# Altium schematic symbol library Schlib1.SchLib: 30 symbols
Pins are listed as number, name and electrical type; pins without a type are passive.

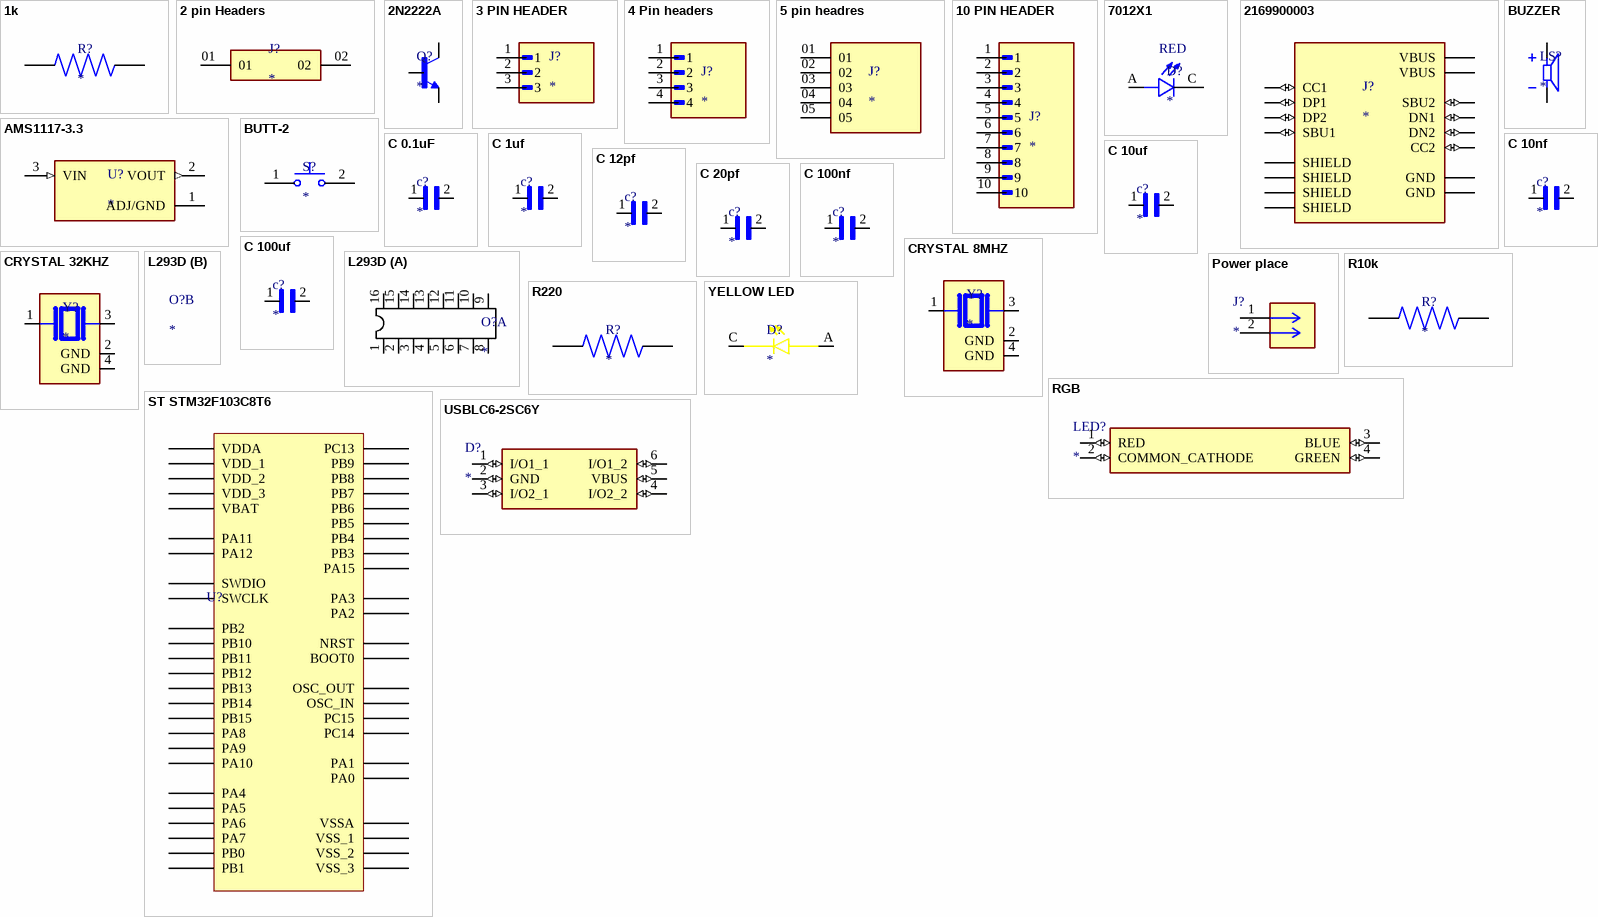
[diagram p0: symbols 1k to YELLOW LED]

## 1k
designator R?
RES, 1K, 1%, 0.1W, 0603, THICK FILM; Resistance: 10kohm; Resistance Tolerance: Â± 1%; Power Rating: 100mW; Resistor Case / Package: 0603 ^1608 Metric]; Resistor Technology: Thick Film; Resistor Type: Genera 67AK7947; MF: Vishay Intertechnology; MP: CRCW060310K0FKECC
footprint RESC1608X55N
pins: 1, 2

## 2 pin Headers
designator J?
Suoolier part number: 952-1902-ND; Manufacturer: Harwin; MP: MTSW-101-09-L-D-515
footprint SAMTEC_MTSW-101-09-L-D-515
pins: 01, 02

## 2N2222A
designator Q?
BJT, TO-92, 40V, 600mA, NPN, 0.625W, 150Â°C; MF: Diotec Semiconductor; MP: 2N2222A
footprint TO92254P470H750-3
pins: 1 E, 2 B, 3 C

## 3 PIN HEADER
designator J?
2.54mm (0.1) Pitch SIL Vertical Throughboard Pin Header, 6.1mm mating pin height, tin, 3 contacts; MF: Harwin; MP: M20-9990346
footprint HARWIN_M20-9990346
pins: 1, 2, 3

## 4 Pin headers
designator J?
1kV 1 2.54mm Pin Header 3A 2.5mm Through Hole 6mm -40℃~+105℃ 3mm Gold 4P 1x4P Through Hole,P=2.54mm Headers, Male Pins; MF: Harwin; MP: M20-9990446
footprint HARWIN_M20-9990446
pins: 1, 2, 3, 4

## 5 pin headres
designator J?
MP: TMS-105-53-G-S
footprint SAMTEC_TMS-105-53-G-S
pins: 01, 02, 03, 04, 05

## 10 PIN HEADER
designator J?
2.00mm (0.079") Pitch SIL Vertical 2.4mm Throughboard Pin Header, 3.5mm mating pin height, gold, 10 contacts; MF: {'manufacturer': u'Harwin Inc.'}; MP: M22-2511005
footprint HARWIN_M22-2511005
pins: 1, 2, 3, 4, 5, 6, 7, 8, 9, 10

## 7012X1
designator D?
Red - LED Indication - Discrete 1.7V 0805 (2012 Metric); MNF PART: YLED0603R; SUP PART: C19171390; MNF: YONGYUTAI
footprint LED_7012X1
pins: A, C

## 2169900003
designator J?
USB-C (USB TYPE-C) USB 2.0 Receptacle Connector 24 (16+8 Dummy) Position Surface Mount, Right Angle; Through Hole; MF: Molex; MP: 2169900003
footprint MOLEX_2169900003
pins: A1_B12 GND (power), A4_B9 VBUS (power), A5 CC1 (io), A6 DP1 (io), A7 DN1 (io), A8 SBU1 (io), B1_A12 GND (power), B4_A9 VBUS (power), B5 CC2 (io), B6 DP2 (io), B7 DN2 (io), B8 SBU2 (io), S1 SHIELD, S2 SHIELD, S3 SHIELD, S4 SHIELD

## AMS1117-3.3
designator U?
Linear Voltage Regulator IC Positive Fixed 1 Output 1A SOT-223-3L; MF: UMW; MP: AMS1117-3.3
footprint SOT229P700X180-4N
pins: 1 ADJ/GND (power), 2 VOUT (out), 3 VIN (in)

## BUTT-2
designator S?
Tactile Switches MINI PUSH BUTTON SWITCH 2-PIN QTY. 4; MF: Gravitech; MP: BUTT-2
footprint SW_BUTT-2
pins: 1, 2

## BUZZER
designator LS?
12 mm, 5 Vdc, 98 dB, Through Hole, Magnetic Audio Indicator Buzzer; MF: Same Sky; MP: CMI-1210-5-95T
footprint XDCR_CMI-1210-5-95T
pins: N, P

## C 0.1uF
designator c?
0.1uFÂ±10% 50V Ceramic Capacitor X7R 0603 (1608 Metric); MF: KEMET; MP: C0603X102K5RAC3316
footprint CAPC1608X90
pins: 1, 2

## C 1uf
designator c?
1uF Â±10% 50V Ceramic Capacitor X7R 0603 (1608 Metric); MF: KEMET; MP: C0603X102K5RAC3316
footprint CAPC1608X90
pins: 1, 2

## C 10nf
designator c?
10nF Â±10% 50V Ceramic Capacitor X7R 0603 (1608 Metric); MF: KEMET; MP: C0603X102K5RAC3316
footprint CAPC1608X90
pins: 1, 2

## C 10uf
designator c?
10uF Â±10% 50V Ceramic Capacitor X7R 0603 (1608 Metric); MF: KEMET; MP: C0603X102K5RAC3316
footprint CAPC1608X90
pins: 1, 2

## C 12pf
designator c?
12PF Â±10% 50V Ceramic Capacitor X7R 0603 (1608 Metric); MF: KEMET; MP: C0603X102K5RAC3316
footprint CAPC1608X90
pins: 1, 2

## C 20pf
designator c?
20PF Â±10% 50V Ceramic Capacitor X7R 0603 (1608 Metric); MF: KEMET; MP: C0603X102K5RAC3316
footprint CAPC1608X90
pins: 1, 2

## C 100nf
designator c?
100nF Â±10% 50V Ceramic Capacitor X7R 0603 (1608 Metric); MF: KEMET; MP: C0603X102K5RAC3316
footprint CAPC1608X90
pins: 1, 2

## C 100uf
designator c?
100uf Â±10% 50V Ceramic Capacitor X7R 0603 (1608 Metric); MF: KEMET; MP: C0603X102K5RAC3316
footprint CAPC1608X90
pins: 1, 2

## CRYSTAL 8MHZ
designator Y?
8 MHz Â±20ppm Crystal 18pF 72 Ohms 4-SMD, No Lead; MP: ABMM2-8.000MHZ-E2-T; MF: Abracon
footprint XTAL_ABMM2-8.000MHZ-E2-T
pins: 1, 2 GND (power), 3 2, 4 GND (power)

## CRYSTAL 32KHZ
designator Y?
32KHz Â±20ppm Crystal 12.5pF 72 Ohms 4-SMD, No Lead; MP: ABMM2-8.000MHZ-E2-T; MF: Abracon
footprint XTAL_ABMM2-8.000MHZ-E2-T
pins: 1, 2 GND (power), 3 2, 4 GND (power)

## L293D
designator O?
footprint DIP880W50P254L2000H510Q16
part A pins: 1 ENABLE 1,2, 2 INPUT 1, 3 OUTPUT 1, 4 GND, 5 GND, 6 OUTPUT 2, 7 INPUT 2, 8 VCC 2, 9 Enable 3,4, 10 INPUT 3, 11 OUTPUT 3, 12 GND, 13 GND, 14 OUTPUT 4, 15 INPUT 4, 16 VCC 1

## Power place
designator J?
2 Position Wire to Board Terminal Block Horizontal with Board 0.250" (6.35mm) Through Hole; MP: 393800102
footprint CONN2_0393800102_524X492_MOL
pins: 1, 2

## R10k
designator R?
RES, 10K, 1%, 0.1W, 0603, THICK FILM; Resistance: 10kohm; Resistance Tolerance: Â± 1%; Power Rating: 100mW; Resistor Case / Package: 0603 ^1608 Metric]; Resistor Technology: Thick Film; Resistor Type: Genera 67AK7947; MF: Vishay Intertechnology; MP: CRCW060310K0FKECC
footprint RESC1608X55N
pins: 1, 2

## R220
designator R?
RES, 220OHM, 1%, 0.1W, 0603, THICK FILM; Resistance: 10kohm; Resistance Tolerance: Â± 1%; Power Rating: 100mW; Resistor Case / Package: 0603 ^1608 Metric]; Resistor Technology: Thick Film; Resistor Type: Genera 67AK7947; MF: Vishay Intertechnology; MP: CRCW060310K0FKECC
footprint RESC1608X55N
pins: 1, 2

## RGB
designator LED?
Red, Green, Blue (RGB) 630nm Red, 525nm Green, 465nm Blue LED Indication - Discrete 1.9V Red, 3.3V Green, 3.3V Blue Radial - 4 Leads; MF: Kingbright; MP: WP154A4SUREQBFZGW
footprint L-154A4SUREQBFZGEC
pins: 1 RED (io), 2 COMMON_CATHODE (io), 3 BLUE (io), 4 GREEN (io)

## ST STM32F103C8T6
designator U?  (value not drawn)
Medium-density performance line Arm-based 32-bit MCU with 64 or 128 KB Flash, USB, CAN, 7 timers, 2 ADCs, 9 com. interfaces; Manufacturer: ST; MPN: STM32F103C8T6
footprint STM
pins: 1 VBAT, 2 PC13, 3 PC14, 4 PC15, 5 OSC_IN, 6 OSC_OUT, 7 NRST, 8 VSSA, 9 VDDA, 10 PA0, 11 PA1, 12 PA2, 13 PA3, 14 PA4, 15 PA5, 16 PA6, 17 PA7, 18 PB0, 19 PB1, 20 PB2, 21 PB10, 22 PB11, 23 VSS_1, 24 VDD_1, 25 PB12, 26 PB13, 27 PB14, 28 PB15, 29 PA8, 30 PA9, 31 PA10, 32 PA11, 33 PA12, 34 SWDIO, 35 VSS_2, 36 VDD_2, 37 SWCLK, 38 PA15, 39 PB3, 40 PB4, 41 PB5, 42 PB6, 43 PB7, 44 BOOT0, 45 PB8, 46 PB9, 47 VSS_3, 48 VDD_3

## USBLC6-2SC6Y
designator D?
17V Clamp 5A (8/20µs) Ipp Tvs Diode Surface Mount SOT-23-6; MF: STMicroelectronics; MP: USBLC6-2SC6Y
footprint SOT95P280X145-6N
pins: 1 I/O1_1 (io), 2 GND (io), 3 I/O2_1 (io), 4 I/O2_2 (io), 5 VBUS (io), 6 I/O1_2 (io)

## YELLOW LED
designator D?
Red 617nm Yellow LED Indication - Discrete 2V Radial; MP: WP7113ID; MF: Kingbright
footprint LED_7012X1
pins: A, C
